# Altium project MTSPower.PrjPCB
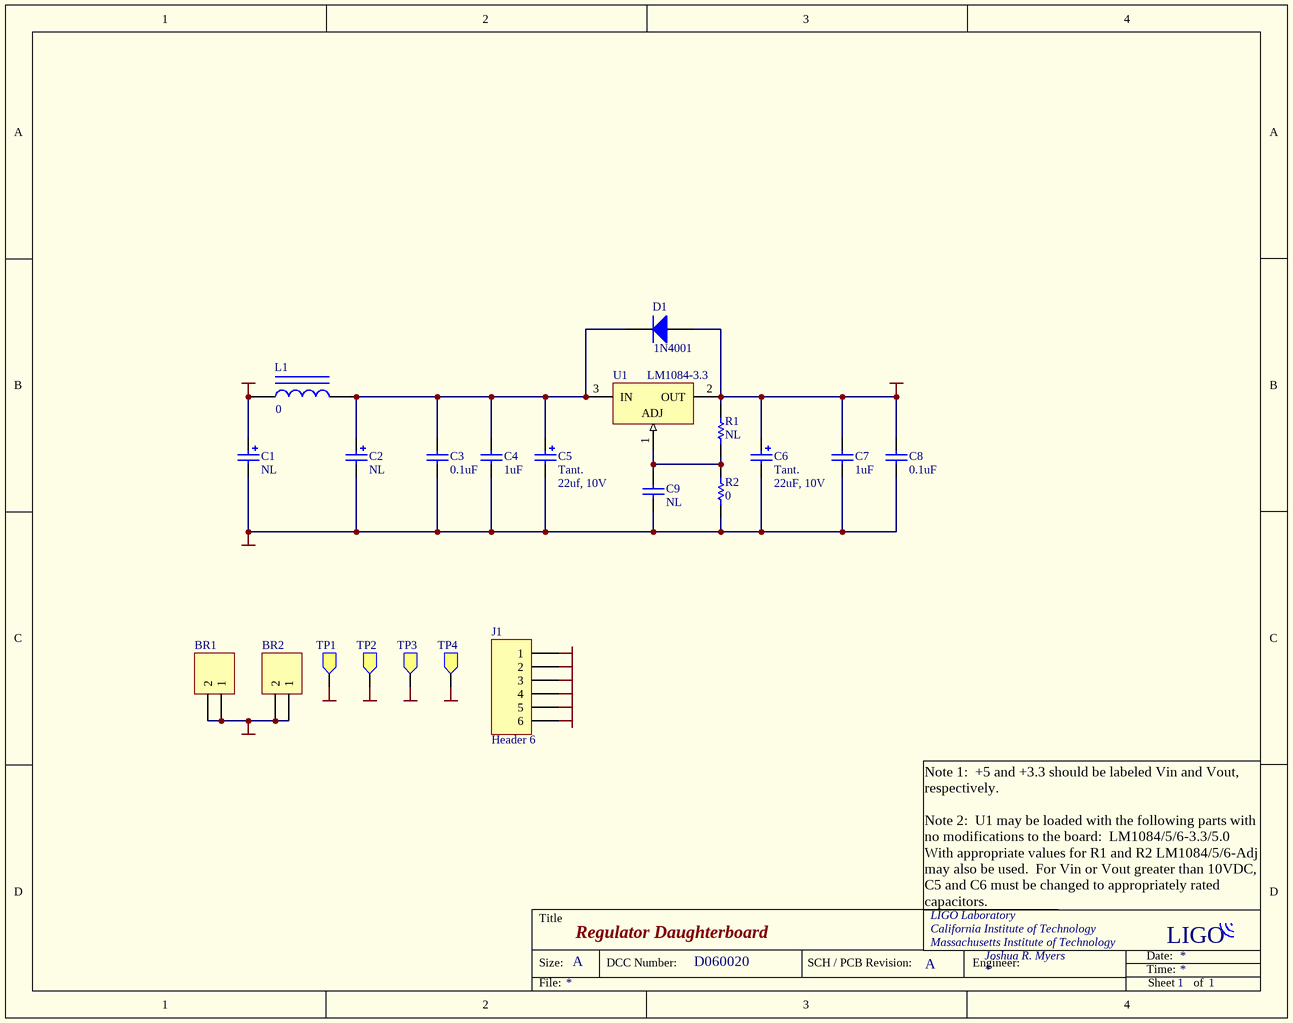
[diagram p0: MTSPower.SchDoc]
1 sheet, 21 parts. Net scope: global (net labels, ports and power ports of the same name join across sheets).
Board file: MTSPower.PCBDOC

## Sheet MTSPower.SchDoc: Regulator Daughterboard
size A; CompanyName: LIGO Hanford Observatory; Engineer: Joshua R. Myers; Organization: LIGO Laboratory; Address1: California Institute of Technology; Address2: Massachusetts Institute of Technology; Address3: Joshua R. Myers; DocumentNumber: D060020; Revision: A; SheetNumber: 1; SheetTotal: 1; PageSetup: Record=PageOptions|CenterHorizontal=True|CenterVertical=True|PrintScale=1.12|XCorrection=1.00|YCorrection=1.00|PrintKind=2|BorderSize=5000000|LeftOffset=0|BottomOffset=0|Orientation=2|PaperLength=1000|PaperWidth=1000|Scale=100|PaperSource=15|PrintQuality=600|MediaType=1|DitherType=10|PaperKind=Letter|PrintScaleMode=1

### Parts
BR1  Header 2  [RA Bracket]  (value not drawn)
BR2  Header 2  [RA Bracket]  (value not drawn)
C1  NL  [CC3216-1206]
C2  NL  [CC3216-1206]
C3  value 0.1uF  [CR3216-1206]  (hidden comment: 4.7uF)
C4  value 1uF  [CR3216-1206]  (hidden comment: 4.7uF)
C5  Tant.  value 22uf, 10V  [2512_1206]
C6  Tant.  value 22uF, 10V  [2512_1206]
C7  value 1uF  [CR3216-1206]  (hidden comment: 4.7uF)
C8  value 0.1uF  [CR3216-1206]  (hidden comment: 4.7uF)
C9  value NL  [CR3216-1206]  (hidden comment: 4.7uF)
D1  1N4001  [DIO10.46-5.3x2.8]
J1  Header 6  [TB Header, 6 Pos]
L1  0  [CR3232-1212]
R1  NL  [CR3216-1206]
R2  0  [CR3216-1206]
TP1  +3.3  [TP1]  (value not drawn)
TP2  GND  [TP1]  (value not drawn)
TP3  +5  [TP1]  (value not drawn)
TP4  GND  [TP1]  (value not drawn)
U1  LM1084-3.3  [TO-220+BHS]

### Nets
+3.3: C6.1 C7.2 C8.2 D1.1(A) J1.3 R1.2 TP1.1 U1.2(OUT)
+5: C1.1 J1.1 J1.5 L1.1 TP3.1
GND: BR1.1 BR1.2 BR2.1 BR2.2 C1.2 C2.2 C3.1 C4.1 C5.2 C6.2 C7.1 C8.1 C9.1 J1.2 J1.4 J1.6 R2.1 TP2.1 TP4.1
NetC2_1: C2.1 C3.2 C4.2 C5.1 D1.2(K) L1.2 U1.3(IN)
NetC9_2: C9.2 R1.1 R2.2 U1.1(ADJ)

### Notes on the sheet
- Note 1:  +5 and +3.3 should be labeled Vin and Vout, respectively.
  Note 2:  U1 may be loaded with the following parts with no modifications to the board:  LM1084/5/6-3.3/5.0  With appropriate values for R1 and R2 LM1084/5/6-Adj may also be used.  For Vin or Vout greater than 10VDC, C5 and C6 must be changed to appropriately rated capacitors.

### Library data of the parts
BR1 BR2 = Header 2: Header, 2-Pin
C1 C2 = Cap Pol1: Polarized Capacitor (Radial); Part Number: P922-ND
C3 C4 C7-C9 = Cap Semi: Capacitor (Semiconductor SIM Model)
C5 C6 = Cap Pol1: Polarized Capacitor (Radial)
D1 = Diode 1N4001: 1 Amp General Purpose Rectifier; Part Number: 1N4001GICT-ND; Revision 1: 11-Jul-2000: SIM Model Added.; Revision 2: 17-Jul-2002: Re-released for DXP Platform.; Package Information: Latest Revision: Aug-1999; Code - JEDEC: DO-204-AL
J1 = Header 6: Header, 6-Pin
L1 = Inductor Iron: Magnetic-Core Inductor; Part Number: 1008PS-103KLB
R1 R2 = res1: Resistor
TP1 TP3 = TP: Part Number: 5005K-ND
TP2 TP4 = TP: Part Number: 5006K-ND
U1 = LM317AT: 3-Terminal Adjustable Regulator; Package Information: Latest Revision: 1995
